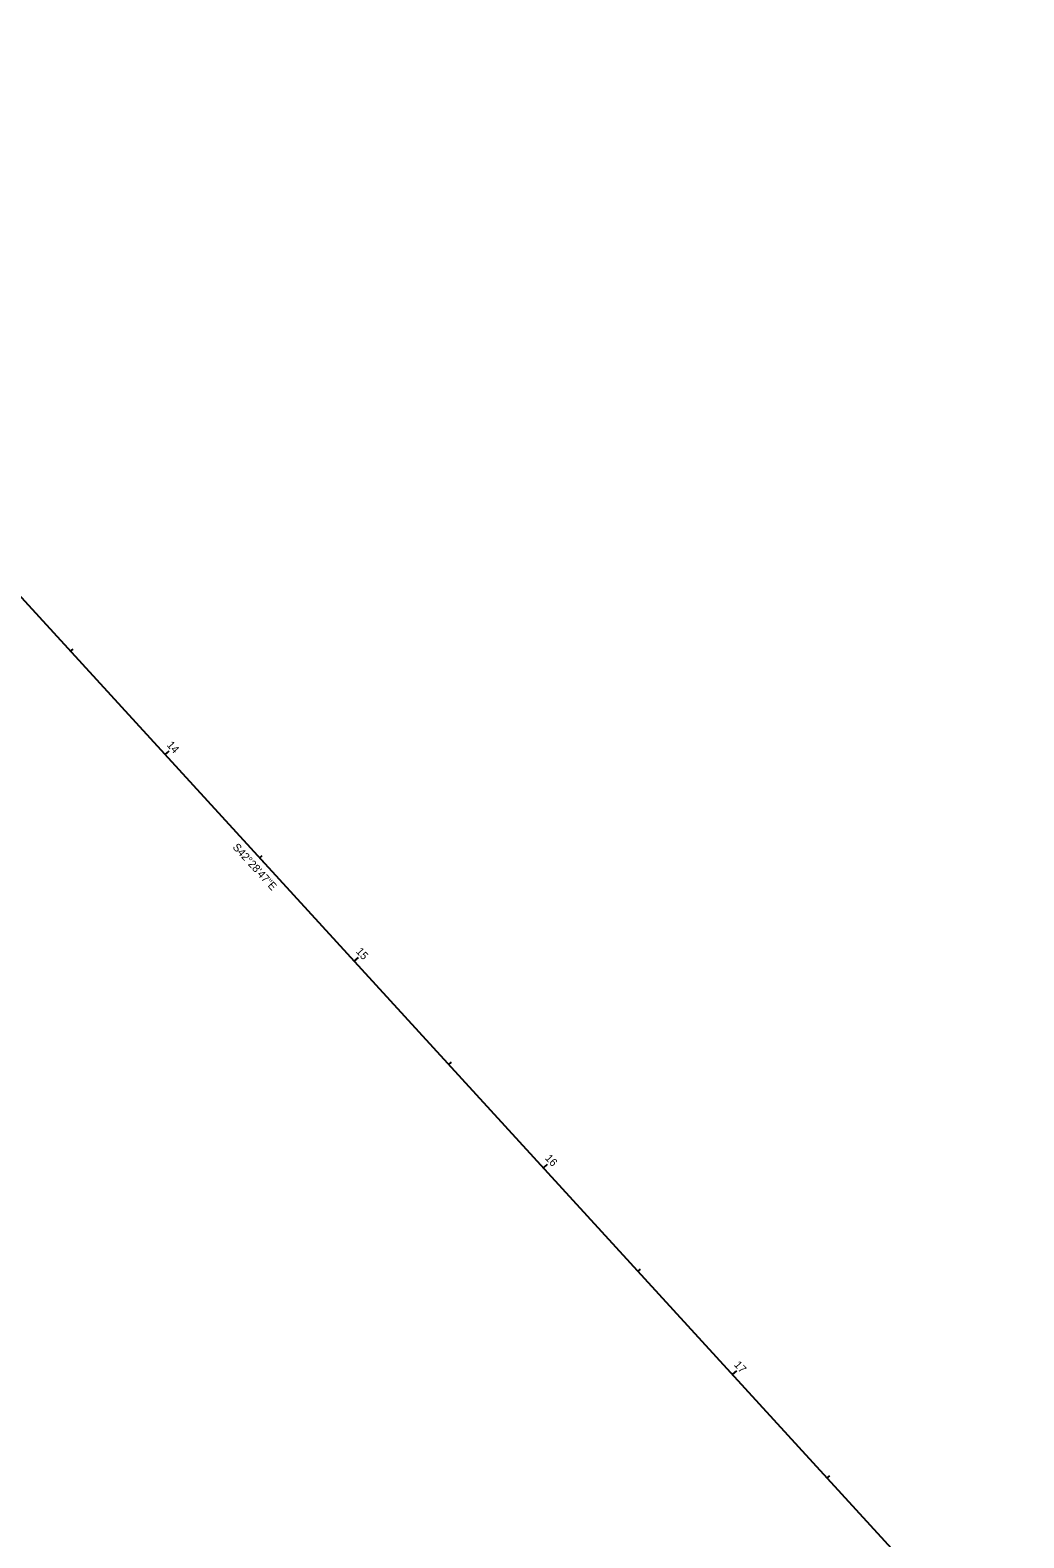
# Model space of a CAD drawing. Extents: x 2196614 to 2198263, y 660890 to 662319.
# Drawn here: x 2197427 to 2197781, y 661437 to 661975 of the extents above; entities that cross this region are included whole.
import ezdxf

# ---------------------------------------------------------------- set-up
doc = ezdxf.new("R2010")
doc.units = 0
for name, color, linetype in [('Default', 7, 'Continuous'), ('GE_X_Alignment', 7, 'Continuous'), ('GE_X_Alignment_1000_Stations', 7, 'Continuous'), ('GE_X_Alignment_100_Stations', 7, 'Continuous'), ('GE_X_Alignment_500_Stations', 7, 'Continuous')]:
    doc.layers.add(name, color=color, linetype=linetype)

msp = doc.modelspace()

# ---------------------------------------------------------------- linework, layer by layer
at = {"layer": 'Default'}
for centre in [(2197474.81, 661716.15), (2197509.73, 661678.01), (2197509.73, 661678.01), (2197509.73, 661678.01), (2197509.73, 661678.01), (2197509.73, 661678.01), (2197509.73, 661678.01), (2197542.34, 661642.4), (2197542.34, 661642.4), (2197609.87, 661568.65), (2197677.41, 661494.9)]:
    msp.add_circle(centre, 0.0000833, dxfattribs=at)
at = {"layer": 'GE_X_Alignment'}
msp.add_line((2197238.07, 661974.69), (2197781.39, 661381.34), dxfattribs=at)
at = {"layer": 'GE_X_Alignment_1000_Stations'}
msp.add_line((2197542.34, 661642.4), (2197543.22, 661643.21), dxfattribs=at)
at = {"layer": 'GE_X_Alignment_100_Stations'}
for p, q in [((2197441.04, 661753.03), (2197441.93, 661753.84)), ((2197474.81, 661716.15), (2197476.28, 661717.5)), ((2197508.57, 661679.28), (2197509.46, 661680.09)), ((2197542.34, 661642.4), (2197543.81, 661643.75)), ((2197576.11, 661605.52), (2197576.99, 661606.34)), ((2197609.87, 661568.65), (2197611.35, 661570)), ((2197643.64, 661531.77), (2197644.52, 661532.58)), ((2197677.41, 661494.9), (2197678.88, 661496.25)), ((2197711.17, 661458.02), (2197712.06, 661458.83))]:
    msp.add_line(p, q, dxfattribs=at)
at = {"layer": 'GE_X_Alignment_500_Stations'}
for p, q in [((2197474.81, 661716.15), (2197475.69, 661716.96)), ((2197542.34, 661642.4), (2197543.81, 661643.75)), ((2197609.87, 661568.65), (2197610.76, 661569.46)), ((2197677.41, 661494.9), (2197678.29, 661495.71))]:
    msp.add_line(p, q, dxfattribs=at)

# ---------------------------------------------------------------- texts
at = {"layer": 'GE_X_Alignment_1000_Stations'}
msp.add_text('S42°28\'47"E', height=2.8, rotation=312.4797, dxfattribs=at).set_placement((2197498.71, 661682.94))
at = {"layer": 'GE_X_Alignment_100_Stations'}
for s, p in [('14', (2197475.2, 661719.43)), ('S42°28\'47"E', (2197498.71, 661682.94)), ('15', (2197542.73, 661645.75)), ('16', (2197610.27, 661571.99)), ('17', (2197677.73, 661498.25))]:
    msp.add_text(s, height=2.8, rotation=312.4797, dxfattribs=at).set_placement(p)
at = {"layer": 'GE_X_Alignment_500_Stations'}
for s, p in [('S42°28\'47"E', (2197498.71, 661682.94)), ('15', (2197542.73, 661645.75))]:
    msp.add_text(s, height=2.8, rotation=312.4797, dxfattribs=at).set_placement(p)

doc.saveas('drawing.dxf')
